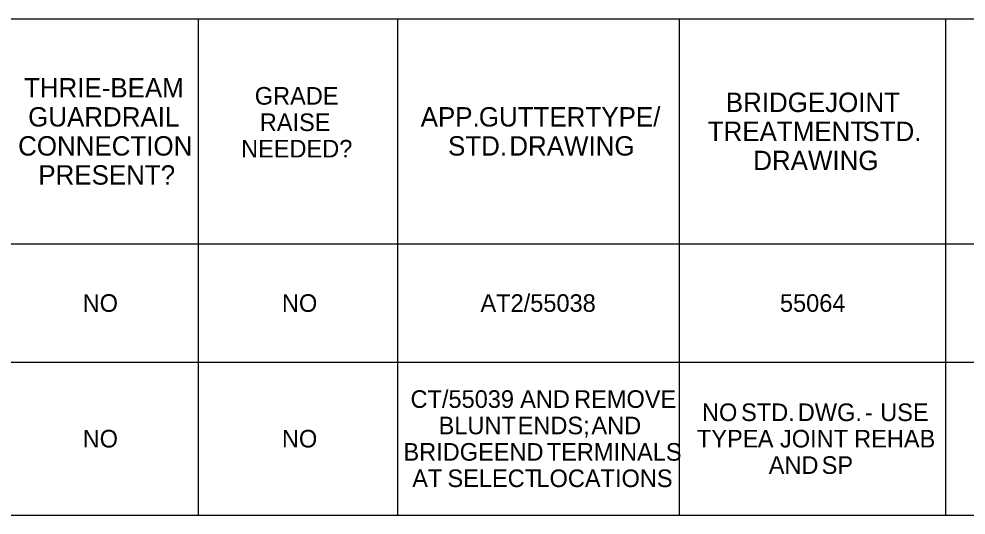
# Model space of a CAD drawing. Extents: x 16 to 1228740, y 11 to 152440.
# Drawn here: x 17.302 to 17.861, y 11.028 to 11.321 of the extents above; entities that cross this region are included whole.
import ezdxf

# ---------------------------------------------------------------- set-up
doc = ezdxf.new("R2010")
doc.units = 0
doc.layers.add('B_Text', color=7, linetype='Continuous')

msp = doc.modelspace()

# ---------------------------------------------------------------- linework, layer by layer
at = {"layer": 'B_Text'}
for p, q in [((16.24983, 11.32083), (17.97565, 11.32083)), ((17.40781, 11.02779), (17.40781, 11.32083)), ((17.52544, 11.02779), (17.52544, 11.32083)), ((17.69173, 11.02779), (17.69173, 11.32083)), ((17.8489, 11.02779), (17.8489, 11.32083)), ((16.24983, 11.188), (17.97565, 11.188)), ((16.24983, 11.188), (17.97565, 11.188)), ((16.24983, 11.11803), (17.97565, 11.11803)), ((16.24983, 11.02779), (17.97565, 11.02779))]:
    msp.add_line(p, q, dxfattribs=at)

# ---------------------------------------------------------------- texts
for s, height, p in [('THRIE-BEAM', 0.01144, (17.30476, 11.27444)), ('GRADE', 0.0104, (17.44098, 11.2702)), ('BRIDGE', 0.01144, (17.71904, 11.26586)), (' JOINT', 0.01144, (17.77343, 11.26586)), ('GUARDRAIL', 0.01144, (17.30723, 11.25728)), ('RAISE', 0.0104, (17.44396, 11.2546)), ('APP.', 0.01144, (17.53894, 11.25728)), (' GUTTER', 0.01144, (17.56902, 11.25728)), (' TYPE/', 0.01144, (17.63197, 11.25728)), ('TREATMENT', 0.01144, (17.70839, 11.2487)), (' STD.', 0.01144, (17.79543, 11.2487)), ('CONNECTION', 0.01144, (17.3013, 11.24012)), ('NEEDED?', 0.0104, (17.4329, 11.239)), ('STD.', 0.01144, (17.55508, 11.24012)), (' DRAWING', 0.01144, (17.58699, 11.24012)), ('DRAWING', 0.01144, (17.73523, 11.23154)), ('PRESENT?', 0.01144, (17.31323, 11.22296)), ('AT2/55038', 0.0104, (17.57423, 11.14782)), ('NO', 0.0104, (17.3394, 11.14782)), ('NO', 0.0104, (17.45702, 11.14782)), ('55064', 0.0104, (17.75099, 11.14782)), ('CT/55039', 0.0104, (17.53294, 11.09111)), (' AND', 0.0104, (17.59378, 11.09111)), (' REMOVE', 0.0104, (17.62563, 11.09111)), ('NO', 0.0104, (17.70497, 11.08331)), (' STD.', 0.0104, (17.72418, 11.08331)), (' DWG.', 0.0104, (17.75766, 11.08331)), (' USE', 0.0104, (17.80629, 11.08331)), (' -', 0.0104, (17.79726, 11.08331)), ('BLUNT', 0.0104, (17.54949, 11.07551)), (' ENDS;', 0.0104, (17.59231, 11.07551)), (' AND', 0.0104, (17.63584, 11.07551)), ('NO', 0.0104, (17.3394, 11.06771)), ('NO', 0.0104, (17.45702, 11.06771)), ('TYPE', 0.0104, (17.70199, 11.06771)), (' A', 0.0104, (17.73404, 11.06771)), (' JOINT', 0.0104, (17.74715, 11.06771)), (' REHAB', 0.0104, (17.79093, 11.06771)), ('BRIDGE', 0.0104, (17.52875, 11.05991)), (' END', 0.0104, (17.5782, 11.05991)), (' TERMINALS', 0.0104, (17.60949, 11.05991)), ('AND', 0.0104, (17.74437, 11.05211)), (' SP', 0.0104, (17.77175, 11.05211)), ('AT', 0.0104, (17.53394, 11.04431)), (' SELECT', 0.0104, (17.55087, 11.04431)), (' LOCATIONS', 0.0104, (17.6034, 11.04431))]:
    msp.add_text(s, height=height, dxfattribs=at).set_placement(p)

doc.saveas('drawing.dxf')
